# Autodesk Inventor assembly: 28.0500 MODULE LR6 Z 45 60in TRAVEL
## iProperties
Created: 2007-07
Part Number: 28.0500 MODULE LR6 Z 45 60in TRAVEL
Document SubType Name: Assembly
Designer: Andy Moles
Author: Andy Moles
